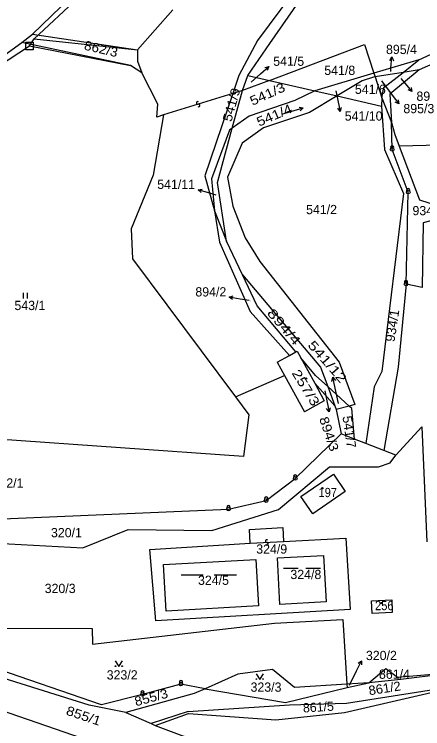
# Model space of a CAD drawing. Extents: x -680102 to -677253, y -1007548 to -1006096.
# Drawn here: x -679518.8 to -679408.3, y -1007390.7 to -1007197.5 of the extents above; entities that cross this region are included whole.
import ezdxf
from ezdxf.enums import TextEntityAlignment as Align

# ---------------------------------------------------------------- set-up
doc = ezdxf.new("R2010")
doc.units = 0
for name, color, linetype, lineweight in [('1', 7, 'Continuous', 25), ('11', 7, 'Continuous', 25), ('16', 7, 'Continuous', 25), ('24', 7, 'Continuous', 25), ('25', 7, 'Continuous', 25), ('35', 7, 'Continuous', 25), ('4', 7, 'Continuous', 25)]:
    doc.layers.add(name, color=color, linetype=linetype, lineweight=lineweight)
doc.layers.add('18', color=7, linetype='Continuous')
doc.layers.add('19', color=7, linetype='Continuous')

msp = doc.modelspace()

# ---------------------------------------------------------------- linework, layer by layer
at = {"layer": '1'}
for p, q in [((-679513.88, -1007202.94), (-679475.39, -1007165.44)), ((-679475.92, -1007196.29), (-679485.49, -1007207.11)), ((-679409.36, -1007209.85), (-679386.69, -1007199.1)), ((-679516.84, -1007205.14), (-679513.88, -1007202.94)), ((-679513.88, -1007202.94), (-679485.49, -1007207.11)), ((-679526.67, -1007212.28), (-679516.84, -1007205.14)), ((-679487.44, -1007211.36), (-679516.84, -1007205.14)), ((-679453.05, -1007204.6), (-679458.08, -1007214.11)), ((-679485.49, -1007207.11), (-679485.49, -1007210.17)), ((-679449.8, -1007215.39), (-679424.08, -1007205.71)), ((-679485.49, -1007210.17), (-679484.3, -1007213.4)), ((-679421.64, -1007214.53), (-679424.73, -1007215.55)), ((-679421.25, -1007214.47), (-679421.64, -1007214.53)), ((-679421.25, -1007214.47), (-679419.43, -1007220.11)), ((-679457.08, -1007218.13), (-679459.73, -1007218.95)), ((-679437.56, -1007218.21), (-679442.92, -1007220.88)), ((-679442.92, -1007220.88), (-679455.33, -1007225.05)), ((-679431.52, -1007219.6), (-679419.51, -1007222.36)), ((-679419.43, -1007220.11), (-679419.51, -1007222.36)), ((-679419.43, -1007220.11), (-679416.79, -1007226.78)), ((-679419.51, -1007222.36), (-679418.66, -1007234.09)), ((-679478.48, -1007224.75), (-679480.3, -1007225.31)), ((-679460.62, -1007228.9), (-679465.46, -1007242.04)), ((-679418.66, -1007234.09), (-679413.58, -1007245.99)), ((-679397.84, -1007232.76), (-679414.73, -1007233.19)), ((-679465.46, -1007242.04), (-679464.65, -1007250.72)), ((-679464.65, -1007250.72), (-679461.39, -1007258.87)), ((-679487.2, -1007255.56), (-679486.86, -1007263.64)), ((-679437.32, -1007295.25), (-679441.32, -1007290.48)), ((-679441.32, -1007290.48), (-679437.57, -1007297.32)), ((-679447.73, -1007291.61), (-679445.76, -1007295.2)), ((-679459.02, -1007301.02), (-679445.76, -1007295.2)), ((-679445.76, -1007295.2), (-679440.36, -1007305.03)), ((-679437.57, -1007297.32), (-679434.97, -1007302.07)), ((-679437.57, -1007297.32), (-679432.09, -1007303.42)), ((-679421.5, -1007298.31), (-679423.7, -1007313.62)), ((-679434.97, -1007302.07), (-679440.36, -1007305.03)), ((-679427.49, -1007304.15), (-679428.23, -1007303.48)), ((-679426.81, -1007312.41), (-679427.49, -1007304.15)), ((-679455.42, -1007305.85), (-679456.86, -1007317.08)), ((-679431.72, -1007304.4), (-679430.45, -1007311)), ((-679415.6, -1007316.76), (-679408.6, -1007309.08)), ((-679408.6, -1007309.08), (-679407.23, -1007340.23)), ((-679456.86, -1007317.08), (-679535.21, -1007311.65)), ((-679442.85, -1007323.05), (-679430.45, -1007311)), ((-679426.81, -1007312.41), (-679430.45, -1007311)), ((-679423.7, -1007313.62), (-679426.81, -1007312.41)), ((-679418.86, -1007315.49), (-679423.7, -1007313.62)), ((-679429.92, -1007361.19), (-679428.85, -1007378.7)), ((-679467.21, -1007379.92), (-679473.75, -1007378.67)), ((-679429.51, -1007386.31), (-679396.69, -1007378.79)), ((-679428.99, -1007383.8), (-679396.69, -1007378.79)), ((-679428.85, -1007378.7), (-679428.8, -1007379.58)), ((-679428.8, -1007379.58), (-679422.91, -1007378.34)), ((-679471.78, -1007386.04), (-679481.84, -1007389.37)), ((-679480.71, -1007389.87), (-679471.67, -1007386.62)), ((-679471.67, -1007386.62), (-679448.1, -1007388.32)), ((-679448.1, -1007388.32), (-679429.51, -1007386.31)), ((-679480.71, -1007389.87), (-679392.55, -1007422.66))]:
    msp.add_line(p, q, dxfattribs=at)
for points in [[(-679281.81, -1007027.69), (-679288.12, -1007026.06), (-679300.13, -1007025.55), (-679317.23, -1007033.9), (-679328.22, -1007036.44), (-679338.3, -1007036.24), (-679352.63, -1007045.79), (-679380.01, -1007071.86), (-679387.43, -1007092.29), (-679392.71, -1007125.35), (-679397.19, -1007140.32), (-679410.92, -1007159.43), (-679421.1, -1007177.36), (-679440.73, -1007187.9), (-679453.05, -1007204.6)], [(-679302.96, -1007300.22), (-679312.75, -1007274.71), (-679319.66, -1007271.06), (-679314.77, -1007239.17), (-679310.61, -1007215.32), (-679322.2, -1007213.64), (-679313.91, -1007175.32), (-679331.07, -1007172.92), (-679359.5, -1007170.05), (-679369.48, -1007182.54), (-679372.06, -1007191.61), (-679384.55, -1007201.63), (-679409.35, -1007212.56), (-679417.25, -1007219.13), (-679416.79, -1007226.78)], [(-679455.65, -1007214.04), (-679449.69, -1007205.42), (-679438.39, -1007189.02), (-679418.03, -1007179.85)], [(-679424.08, -1007205.71), (-679421.57, -1007213.47), (-679421.25, -1007214.47)], [(-679480.3, -1007225.31), (-679480.05, -1007221.83), (-679484.3, -1007213.4), (-679487.44, -1007211.36)], [(-679409.36, -1007209.85), (-679421.57, -1007213.47), (-679437.56, -1007218.21)], [(-679419.43, -1007220.11), (-679418.89, -1007217.36), (-679413.68, -1007213.26), (-679409.36, -1007209.85)], [(-679409.35, -1007212.56), (-679413.68, -1007213.26), (-679421.25, -1007214.47)], [(-679458.08, -1007214.11), (-679459.73, -1007218.95), (-679467.34, -1007241.21)], [(-679449.8, -1007215.39), (-679437.56, -1007218.21), (-679431.52, -1007219.6)], [(-679424.73, -1007215.55), (-679431.52, -1007219.6), (-679438.99, -1007224.05)], [(-679463.9, -1007243.05), (-679459.88, -1007228.36), (-679457.08, -1007218.13)], [(-679478.48, -1007224.75), (-679481.25, -1007241.02), (-679487.2, -1007255.56)], [(-679438.99, -1007224.05), (-679451.41, -1007228.22), (-679457.18, -1007232.42), (-679461.12, -1007241.55), (-679459.73, -1007249.43), (-679456.37, -1007257.97), (-679452.4, -1007264.34), (-679430.98, -1007291.65), (-679426.69, -1007303.08)], [(-679455.33, -1007225.05), (-679459.88, -1007228.36), (-679460.62, -1007228.9)], [(-679408.49, -1007271.44), (-679412.87, -1007270.49), (-679412.28, -1007245.62), (-679416.63, -1007234.08), (-679416.79, -1007226.78), (-679415.92, -1007230.06)], [(-679415.92, -1007230.06), (-679414.73, -1007233.19), (-679409.23, -1007247.72)], [(-679467.34, -1007241.21), (-679464.65, -1007250.72), (-679463.37, -1007259.18)], [(-679442.69, -1007288.84), (-679453.14, -1007276.35), (-679457.07, -1007268.02), (-679461.39, -1007258.87), (-679463.9, -1007243.05)], [(-679413.58, -1007245.99), (-679419.37, -1007294.15), (-679421.5, -1007298.31)], [(-679409.23, -1007247.72), (-679399.97, -1007250.68), (-679398.04, -1007251.22), (-679408.21, -1007253.91), (-679408.49, -1007271.44)], [(-679463.37, -1007259.18), (-679455.02, -1007277.92), (-679444.37, -1007289.76)], [(-679486.86, -1007263.64), (-679459.02, -1007301.02), (-679455.42, -1007305.85)], [(-679457.07, -1007268.02), (-679435.97, -1007292.95), (-679434.04, -1007298.22)], [(-679412.87, -1007270.49), (-679414.99, -1007292.97), (-679418.86, -1007315.49)], [(-679442.69, -1007288.84), (-679442.34, -1007288.65), (-679441.32, -1007290.48)], [(-679447.73, -1007291.61), (-679444.37, -1007289.76), (-679442.69, -1007288.84)], [(-679428.23, -1007303.48), (-679434.04, -1007298.22), (-679437.32, -1007295.25)], [(-679434.04, -1007298.22), (-679432.09, -1007303.42), (-679431.72, -1007304.4)], [(-679426.69, -1007303.08), (-679428.23, -1007303.48), (-679431.72, -1007304.4)], [(-679530.41, -1007340.21), (-679500.33, -1007341.85), (-679488.03, -1007336.83), (-679465.4, -1007337.14), (-679447.34, -1007331.48), (-679433.57, -1007319.93), (-679420.33, -1007319.87), (-679417.19, -1007318.87), (-679415.6, -1007316.76), (-679418.86, -1007315.49)], [(-679530.47, -1007334.35), (-679460.89, -1007331.33), (-679450.72, -1007329.05), (-679442.85, -1007323.05)], [(-679488.66, -1007386.35), (-679498.55, -1007384.38), (-679529.47, -1007374.69), (-679551.85, -1007367.67), (-679565.44, -1007361.02), (-679578.65, -1007354.47), (-679594.66, -1007344.79), (-679604.38, -1007341.08)], [(-679495.26, -1007384.27), (-679525.72, -1007373.79), (-679564.14, -1007360.58)], [(-679522.79, -1007373.09), (-679536.5, -1007363.53), (-679497.8, -1007363.63), (-679497.7, -1007367.9), (-679448.44, -1007362.22), (-679429.92, -1007361.19)], [(-679557.5, -1007373.16), (-679549.86, -1007376.28), (-679549.6, -1007376.39), (-679409.65, -1007424.66), (-679396.29, -1007429.27), (-679283.7, -1007440.7), (-679277.3, -1007443.79), (-679273.41, -1007446.8)], [(-679443, -1007379.55), (-679449.03, -1007374.74), (-679458.33, -1007375.97), (-679467.21, -1007379.92), (-679470.22, -1007381.26), (-679488.66, -1007386.35)], [(-679399.37, -1007375.35), (-679402.68, -1007375.99), (-679414.28, -1007377.44), (-679422.91, -1007378.34), (-679418.33, -1007374.49), (-679415.13, -1007376.82)], [(-679415.13, -1007376.82), (-679406.74, -1007376.04), (-679399.37, -1007375.35)], [(-679473.75, -1007378.67), (-679484.14, -1007381.47), (-679495.26, -1007384.27)], [(-679422.91, -1007378.34), (-679428.85, -1007378.7), (-679443, -1007379.55)], [(-679467.21, -1007379.92), (-679445.46, -1007383.67), (-679428.8, -1007379.58)], [(-679471.78, -1007386.04), (-679444.35, -1007384.24), (-679428.99, -1007383.8)], [(-679488.66, -1007386.35), (-679481.84, -1007389.37), (-679480.71, -1007389.87)]]:
    msp.add_lwpolyline(points, dxfattribs=at)
for points in [[(-679457.08, -1007218.13), (-679455.65, -1007214.04), (-679449.8, -1007215.39)], [(-679432.51, -1007321.9), (-679429.29, -1007326.6), (-679438.11, -1007332.63), (-679441.36, -1007327.95)], [(-679482.19, -1007342.26), (-679455, -1007340.6), (-679455.21, -1007336.86), (-679446.18, -1007336.33), (-679446.05, -1007340.09), (-679429.17, -1007339.2), (-679427.99, -1007358.5), (-679480.52, -1007361.56)], [(-679447.66, -1007344.56), (-679435.18, -1007343.85), (-679434.46, -1007356.47), (-679446.96, -1007357.17)], [(-679478.44, -1007346.35), (-679453.5, -1007344.95), (-679452.77, -1007357.51), (-679477.73, -1007358.93)], [(-679422.17, -1007356.2), (-679416.68, -1007355.92), (-679416.57, -1007359.29), (-679422, -1007359.59)]]:
    msp.add_lwpolyline(points, close=True, dxfattribs=at)
at = {"layer": '11'}
for p, q in [((-679474.58, -1007167.77), (-679513.45, -1007204.14)), ((-679514.72, -1007206.1), (-679513.45, -1007204.14)), ((-679513.45, -1007204.14), (-679485.49, -1007207.11))]:
    msp.add_line(p, q, dxfattribs=at)
msp.add_lwpolyline([(-679588.85, -1007241.34), (-679555.81, -1007229.66), (-679541.1, -1007222.54), (-679535.31, -1007219.48), (-679526.32, -1007213.61), (-679514.72, -1007206.1), (-679487.44, -1007211.36)], dxfattribs=at)
at = {"layer": '16'}
for p, q in [((-679416.93, -1007212.06), (-679416.659, -1007209.073)), ((-679452.25, -1007213.64), (-679449.993, -1007211.664)), ((-679417.01, -1007213.01), (-679416.93, -1007212.06)), ((-679454.76, -1007215.84), (-679452.25, -1007213.64)), ((-679414.25, -1007214.9), (-679413.19, -1007216.14)), ((-679419.48, -1007215.48), (-679416.57, -1007219.38)), ((-679413.19, -1007216.14), (-679411.25, -1007218.428)), ((-679431.83, -1007218.19), (-679431.27, -1007220.84)), ((-679431.27, -1007220.84), (-679430.657, -1007223.776)), ((-679416.57, -1007219.38), (-679414.778, -1007221.785)), ((-679466.27, -1007245.83), (-679469.144, -1007244.973)), ((-679464.21, -1007246.44), (-679466.27, -1007245.83)), ((-679457.73, -1007274.53), (-679460.689, -1007274.041)), ((-679455.34, -1007274.92), (-679457.73, -1007274.53)), ((-679432.03, -1007298.64), (-679432.669, -1007295.709)), ((-679434.86, -1007299.38), (-679434.3, -1007302.08)), ((-679431.13, -1007302.77), (-679432.03, -1007298.64)), ((-679434.3, -1007302.08), (-679433.692, -1007305.017)), ((-679426.25, -1007375.06), (-679424.903, -1007372.38)), ((-679428.2, -1007378.96), (-679426.25, -1007375.06))]:
    msp.add_line(p, q, dxfattribs=at)
for points in [[(-679417.246, -1007210.023), (-679416.659, -1007209.073), (-679416.251, -1007210.114)], [(-679451.075, -1007211.947), (-679449.993, -1007211.664), (-679450.416, -1007212.699)], [(-679411.516, -1007217.341), (-679411.25, -1007218.428), (-679412.278, -1007217.988)], [(-679414.974, -1007220.684), (-679414.778, -1007221.785), (-679415.776, -1007221.282)], [(-679430.372, -1007222.695), (-679430.657, -1007223.776), (-679431.35, -1007222.899)], [(-679468.329, -1007245.738), (-679469.144, -1007244.973), (-679468.043, -1007244.78)], [(-679459.784, -1007274.696), (-679460.689, -1007274.041), (-679459.621, -1007273.711)], [(-679432.944, -1007296.793), (-679432.669, -1007295.709), (-679431.968, -1007296.58)], [(-679433.405, -1007303.937), (-679433.692, -1007305.017), (-679434.384, -1007304.139)], [(-679425.799, -1007373.049), (-679424.903, -1007372.38), (-679424.905, -1007373.498)]]:
    msp.add_lwpolyline(points, dxfattribs=at)
at = {"layer": '24'}
for centre, radius in [((-679416.63, -1007234.08), 0.5), ((-679416.63, -1007234.08), 0.022), ((-679412.28, -1007245.62), 0.5), ((-679412.28, -1007245.62), 0.022), ((-679412.87, -1007270.49), 0.5), ((-679412.87, -1007270.49), 0.022), ((-679442.85, -1007323.05), 0.5), ((-679442.85, -1007323.05), 0.022), ((-679450.72, -1007329.05), 0.5), ((-679450.72, -1007329.05), 0.022), ((-679460.89, -1007331.33), 0.5), ((-679460.89, -1007331.33), 0.022), ((-679473.75, -1007378.67), 0.5), ((-679473.75, -1007378.67), 0.022), ((-679484.14, -1007381.47), 0.5), ((-679484.14, -1007381.47), 0.022)]:
    msp.add_circle(centre, radius, dxfattribs=at)
for centre in [(-679416.631, -1007233.517), (-679412.281, -1007245.057), (-679412.871, -1007269.927), (-679442.851, -1007322.487), (-679450.721, -1007328.487), (-679460.891, -1007330.767), (-679473.751, -1007378.107), (-679484.141, -1007380.907)]:
    msp.add_arc(centre, 0.437, 328.35109, 209.97456, dxfattribs=at)
at = {"layer": '25'}
for p, q in [((-679446.436, -1007224.552), (-679440.684, -1007222.848)), ((-679516.327, -1007274.345), (-679516.327, -1007272.845)), ((-679515.293, -1007274.345), (-679515.293, -1007272.845)), ((-679446.035, -1007347.29), (-679442.015, -1007347.29)), ((-679440.004, -1007347.29), (-679435.984, -1007347.29)), ((-679473.74, -1007349.12), (-679467.74, -1007349.12)), ((-679464.74, -1007349.12), (-679458.74, -1007349.12))]:
    msp.add_line(p, q, dxfattribs=at)
for points in [[(-679441.785, -1007222.653), (-679440.684, -1007222.848), (-679441.501, -1007223.612)], [(-679491.54, -1007372.4), (-679490.54, -1007373.9), (-679489.54, -1007372.4)], [(-679453.45, -1007375.91), (-679452.45, -1007377.41), (-679451.45, -1007375.91)]]:
    msp.add_lwpolyline(points, dxfattribs=at)
for centre, radius in [((-679439.91, -1007296.05), 0.175), ((-679435.49, -1007325.71), 0.175), ((-679419.56, -1007356.77), 0.175), ((-679491.44, -1007373.8), 0.1), ((-679489.64, -1007373.8), 0.1), ((-679453.35, -1007377.31), 0.1), ((-679451.55, -1007377.31), 0.1)]:
    msp.add_circle(centre, radius, dxfattribs=at)
for centre, radius, start, end in [((-679469.204, -1007221.497), 0.369, 54.71564, 286.46424), ((-679468.994, -1007222.202), 0.367, 234.30774, 106.75981), ((-679450.548, -1007339.983), 0.367, 40.38701, 272.81007), ((-679450.513, -1007340.718), 0.368, 220.60305, 92.64852)]:
    msp.add_arc(centre, radius, start, end, dxfattribs=at)
at = {"layer": '35'}
msp.add_lwpolyline([(-679515.72, -1007205.1), (-679513.72, -1007205.1), (-679513.72, -1007207.1), (-679515.72, -1007207.1)], close=True, dxfattribs=at)
at = {"layer": '4'}
for p, q in [((-679459.73, -1007218.95), (-679478.48, -1007224.75)), ((-679455, -1007340.6), (-679446.05, -1007340.09))]:
    msp.add_line(p, q, dxfattribs=at)

# ---------------------------------------------------------------- texts
at = {"layer": '16'}
for s, p in [('895/4', (-679418.28, -1007208.28)), ('541/5', (-679448.79, -1007211.46)), ('895/2', (-679410.05, -1007220.93)), ('895/3', (-679413.58, -1007224.28)), ('541/10', (-679429.45, -1007226.28)), ('320/2', (-679423.71, -1007372.18))]:
    msp.add_text(s, height=2.5, dxfattribs=at).set_placement(p)
for s, p in [('541/11', (-679469.95, -1007244.77)), ('894/2', (-679461.49, -1007273.84))]:
    msp.add_text(s, height=2.5, dxfattribs=at).set_placement(p, align=Align.RIGHT)
at = {"layer": '16', "width": 1.35}
msp.add_text('541/12', height=2.5, rotation=311.202, dxfattribs=at).set_placement((-679430.554, -1007297.504), align=Align.RIGHT)
at = {"layer": '16', "width": 1.15}
msp.add_text('894/3', height=2.5, rotation=288.502, dxfattribs=at).set_placement((-679436.397, -1007306.852))
at = {"layer": '18'}
for s, height, rotation, width, p in [('862/3', 2.5, 346.803, 1.1, (-679500.13, -1007207.041)), ('895/2', 0.1, 39.7, 1.4, (-679414.224, -1007214.619)), ('541/3', 2.5, 24.2, 1.2, (-679454.43, -1007222.286)), ('541/9', 2.5, 74.501, 1.1, (-679460.119, -1007226.754)), ('541/4', 2.5, 23.1, 1.2, (-679452.645, -1007227.938)), ('541/11', 0.1, 72.001, 1.1, (-679464.338, -1007246.188)), ('894/2', 0.1, 305.202, 1.3, (-679455.062, -1007274.968)), ('894/4', 2.5, 310.602, 1.4, (-679450.648, -1007278.431)), ('541/7', 2.5, 278.402, 1.05, (-679430.073, -1007306.318)), ('861/2', 2.5, 8.9, 1.05, (-679422.784, -1007381.702)), ('855/1', 2.5, 341.303, 1.15, (-679505.047, -1007386.885))]:
    msp.add_text(s, height=height, rotation=rotation, dxfattribs=dict(at, width=width)).set_placement(p)
for s, height, p in [('541/8', 2.5, (-679434.98, -1007213.93)), ('895/4', 0.1, (-679416.81, -1007212.81)), ('895/3', 0.1, (-679419.28, -1007215.28)), ('541/5', 0.1, (-679454.56, -1007215.64)), ('541/6', 2.5, (-679426.69, -1007219.05)), ('541/10', 0.1, (-679431.63, -1007217.99)), ('934/2', 2.5, (-679411.12, -1007251.87)), ('543/1', 2.5, (-679518.81, -1007277.52)), ('894/3', 0.1, (-679434.66, -1007299.18)), ('541/12', 0.1, (-679430.93, -1007302.57)), ('324/9', 2.5, (-679453.39, -1007343.4)), ('324/8', 2.5, (-679444.15, -1007350.27)), ('324/5', 2.5, (-679469.14, -1007351.84)), ('861/4', 2.5, (-679420.18, -1007377.24)), ('323/3', 2.5, (-679454.93, -1007380.74)), ('320/2', 0.1, (-679428, -1007378.76))]:
    msp.add_text(s, height=height, dxfattribs=at).set_placement(p)
for s, p in [('541/2', (-679435.72, -1007251.58)), ('542/1', (-679520.54, -1007325.53)), ('320/1', (-679504.74, -1007338.96)), ('320/3', (-679506.439, -1007354.05)), ('323/2', (-679489.66, -1007377.43))]:
    msp.add_text(s, height=2.5, dxfattribs=at).set_placement(p, align=Align.CENTER)
for s, rotation, width, p in [('934/1', 81.201, 1.05, (-679415.327, -1007281.912)), ('855/3', 15.3, 1.1, (-679481.48, -1007383.483))]:
    msp.add_text(s, height=2.5, rotation=rotation, dxfattribs=dict(at, width=width)).set_placement(p, align=Align.CENTER)
msp.add_text('861/5', height=2.5, rotation=3.4, dxfattribs=at).set_placement((-679440.683, -1007386.359))
at = {"layer": '19', "width": 1.3}
msp.add_text('257/3', height=2.5, rotation=301.702, dxfattribs=at).set_placement((-679443.905, -1007294.525))
at = {"layer": '19', "width": 0.9}
for s, p in [('197', (-679436.55, -1007328.11)), ('256', (-679421.25, -1007358.68))]:
    msp.add_text(s, height=2.5, dxfattribs=at).set_placement(p)

doc.saveas('drawing.dxf')
